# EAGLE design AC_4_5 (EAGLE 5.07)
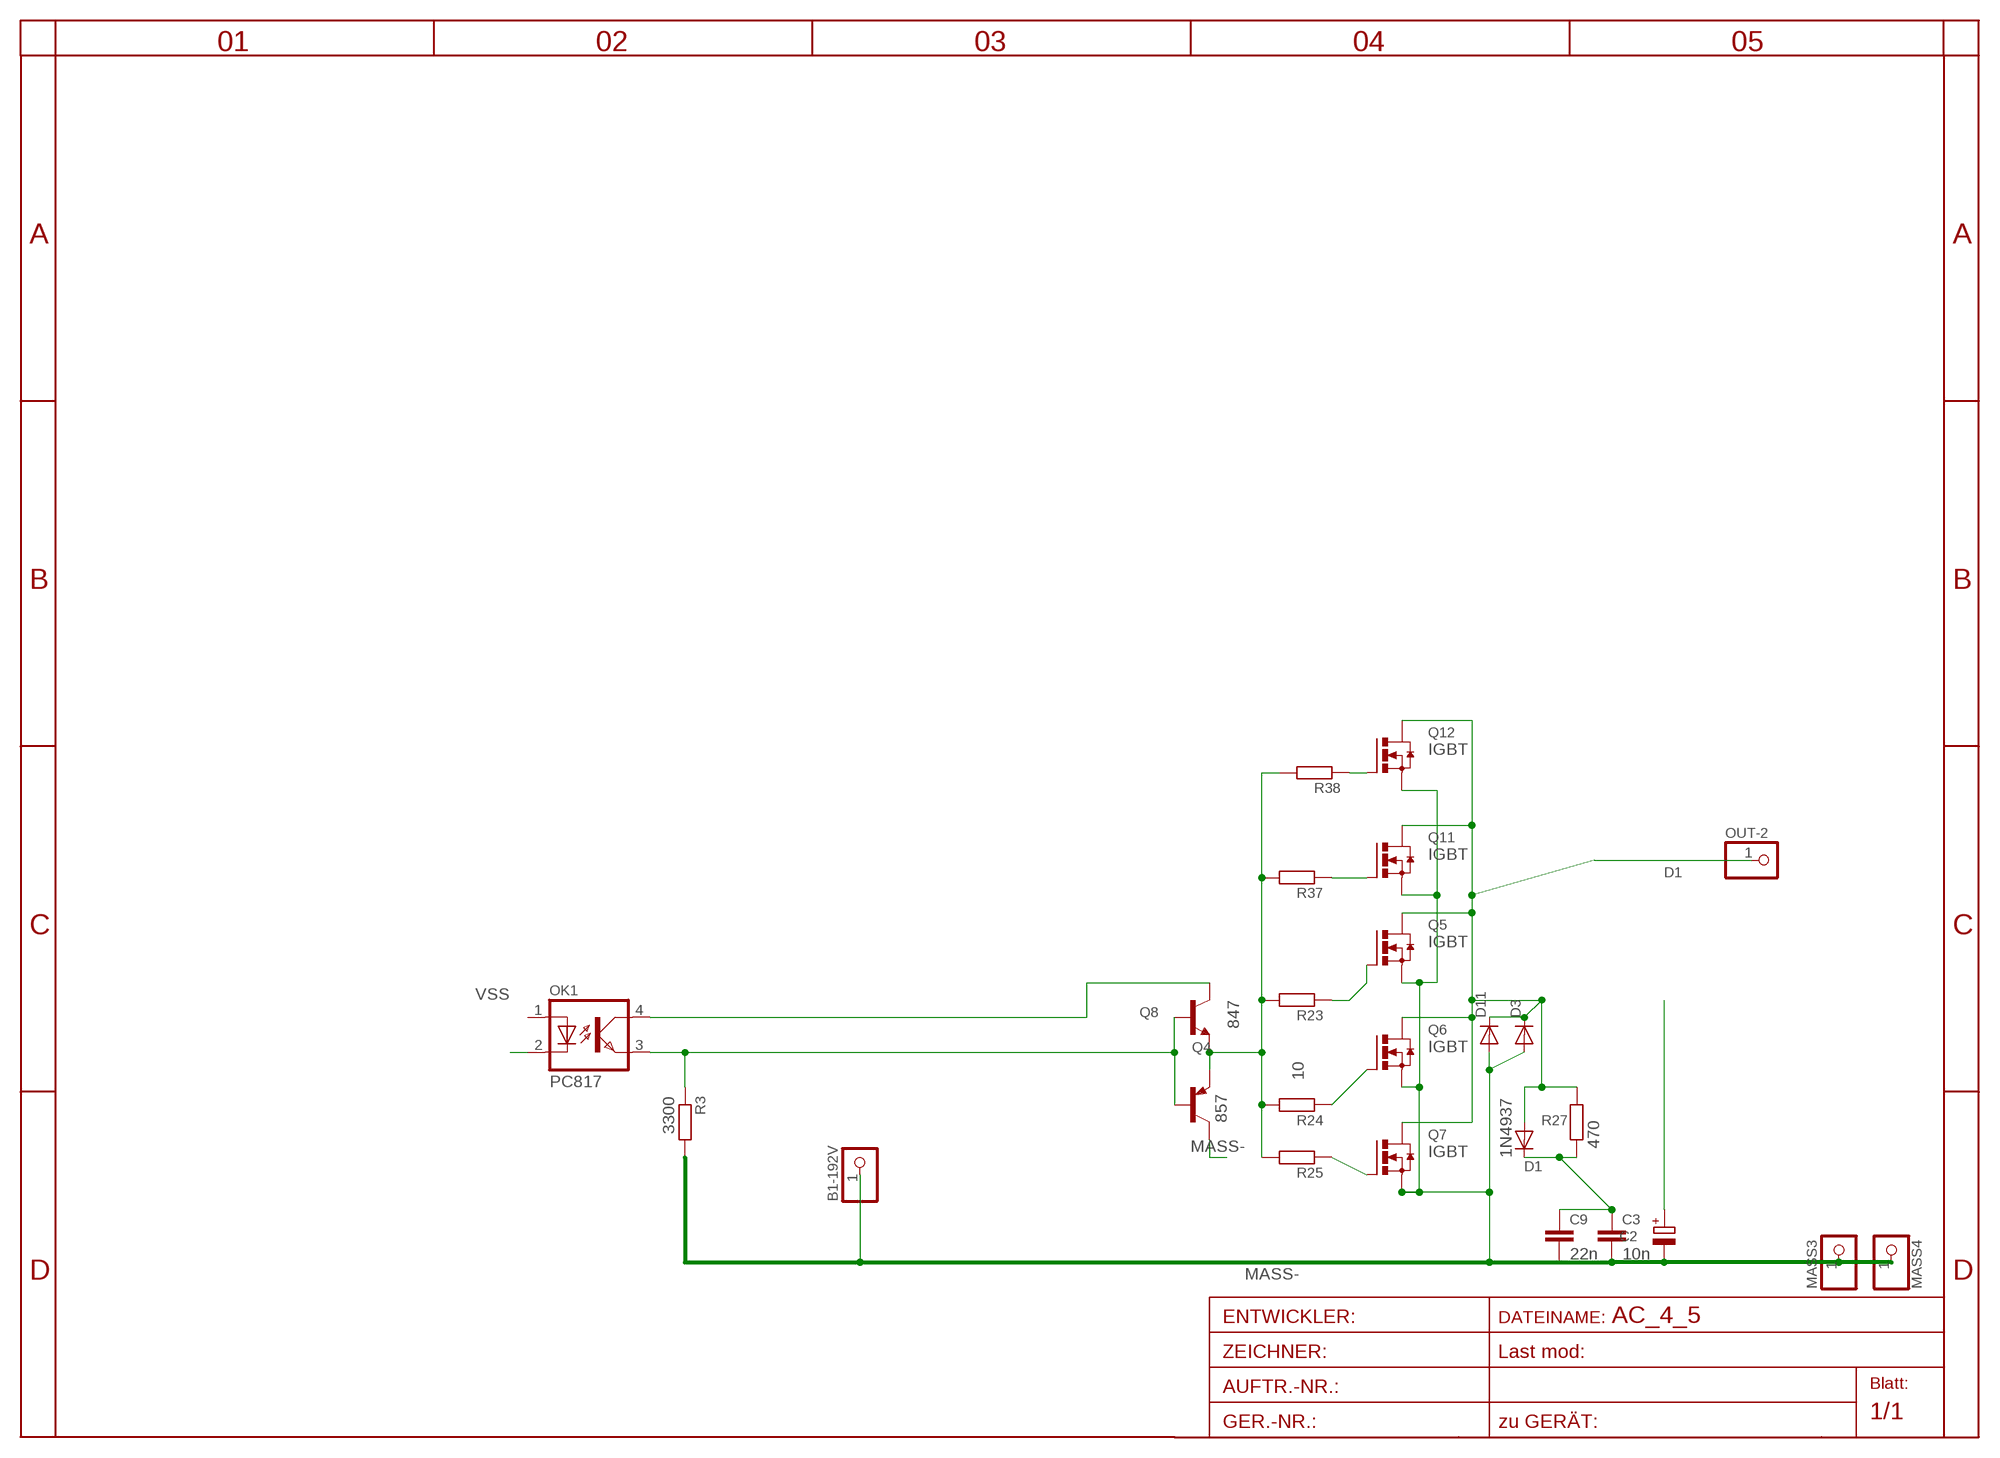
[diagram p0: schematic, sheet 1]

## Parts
B1-192V  PINHD-1X13MM2  [1X3MM2]
C2  CPOL-EUE2.5-5  [E2,5-5]
C3  10n  C-EU025_050-050X075  [C025_050-050X075]
C9  22n  C-EU102-043X133  [C102-043X133]
D1  1N4937  1N4004DO41-10  [DO41-10]
D3  DIODE-SMC  [SMC]
D11  DIODE-SMC  [SMC]
MASS3  PINHD-1X13MM2  [1X3MM2]
MASS4  PINHD-1X13MM2  [1X3MM2]
OK1  PC817  [DIL04]
OUT-2  PINHD-1X13MM2  [1X3MM2]
Q4  857  BC857ALT1SMD  [SOT23-BEC]
Q5  IGBT  N-HEXFET_DPAK-  [TO252]
Q6  IGBT  N-HEXFET_DPAK-  [TO252]
Q7  IGBT  N-HEXFET_DPAK-  [TO252]
Q8  847  BC846ALT1SMD  [SOT23]
Q11  IGBT  N-HEXFET_DPAK-  [TO252]
Q12  IGBT  N-HEXFET_DPAK-  [TO252]
R3  3300  R-EU_R0805  [R0805]
R23  R-EU_0207/12  [0207/12]
R24  R-EU_0207/12  [0207/12]
R25  10  R-EU_0207/12  [0207/12]
R27  470  R-EU_0207/10  [0207/10]
R37  R-EU_0207/12  [0207/12]
R38  R-EU_0207/12  [0207/12]

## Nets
D1: D1.A D3.C D11.C OUT-2.1 Q5.3(D) Q6.3(D) Q7.3(D) Q11.3(D) Q12.3(D) R27.2
EGATE: Q4.E Q8.2(E) R23.2 R24.2 R25.2 R37.2 R38.2
MASS-: B1-192V.1 C2.- C3.3 C9.2 D3.A D11.A MASS3.1 MASS4.1 Q4.C Q5.2(S) Q6.2(S) Q7.2(S) Q11.2(S) Q12.2(S) R3.2
N$2: C3.1 C9.1 D1.C R27.1
N$25: Q12.1(G) R38.1
N$26: Q6.1(G) R24.1
N$27: Q5.1(G) R23.1
N$46: Q11.1(G) R37.1
N$47: Q7.1(G) R25.1
PP1: OK1.3(EMIT) Q4.B Q8.1(B) R3.1
V_OK: C2.+ OK1.4(COL) Q8.3(C)
VSS: OK1.2(C)
Unconnected: OK1.1(A)

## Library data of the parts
B1-192V MASS3 MASS4 OUT-2 = pinhead:PINHD-1X1: PIN HEADER
C2 = rcl-2:CPOL-EU: POLARIZED CAPACITOR, European symbol
C3 C9 = rcl-2:C-EU: CAPACITOR, European symbol
D1 = diode:1N4004: DIODE
D3 D11 = diode:DIODE-: DIODE
OK1 = optocoupler:PC817: SHARP OPTO COUPLER
Q4 = transistor-pnp:BC857*: PNP Transistror
Q5-Q7 Q11 Q12 = transistor-power:N-HEXFET_?-*: HEXFET® Power MOSFET
Q8 = transistor-npn:BC846*: NPN Transistor
R3 R23-R25 R27 R37 R38 = rcl-2:R-EU_: RESISTOR, European symbol

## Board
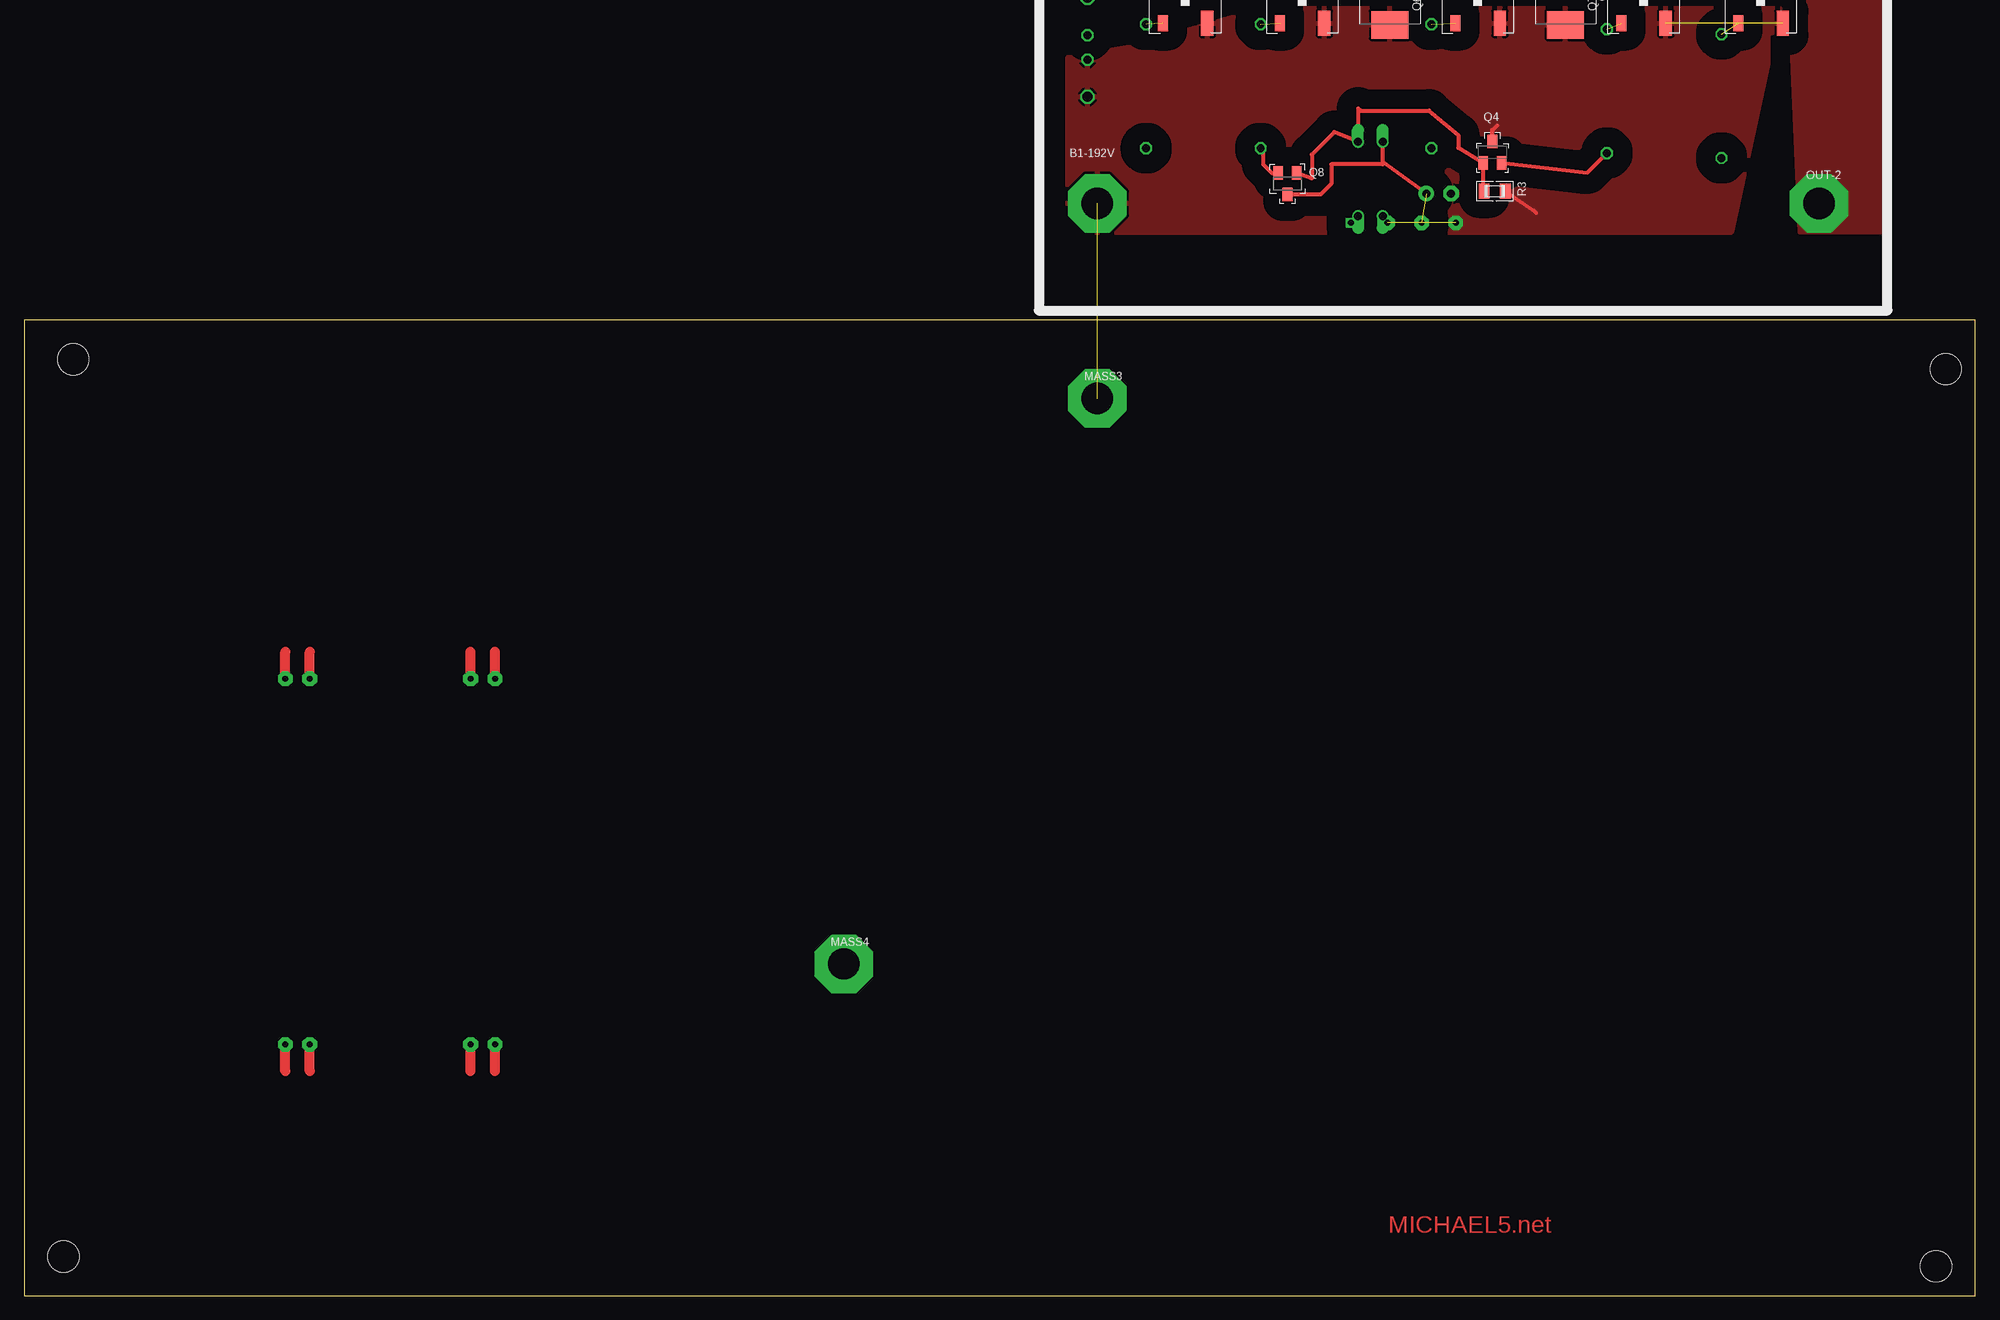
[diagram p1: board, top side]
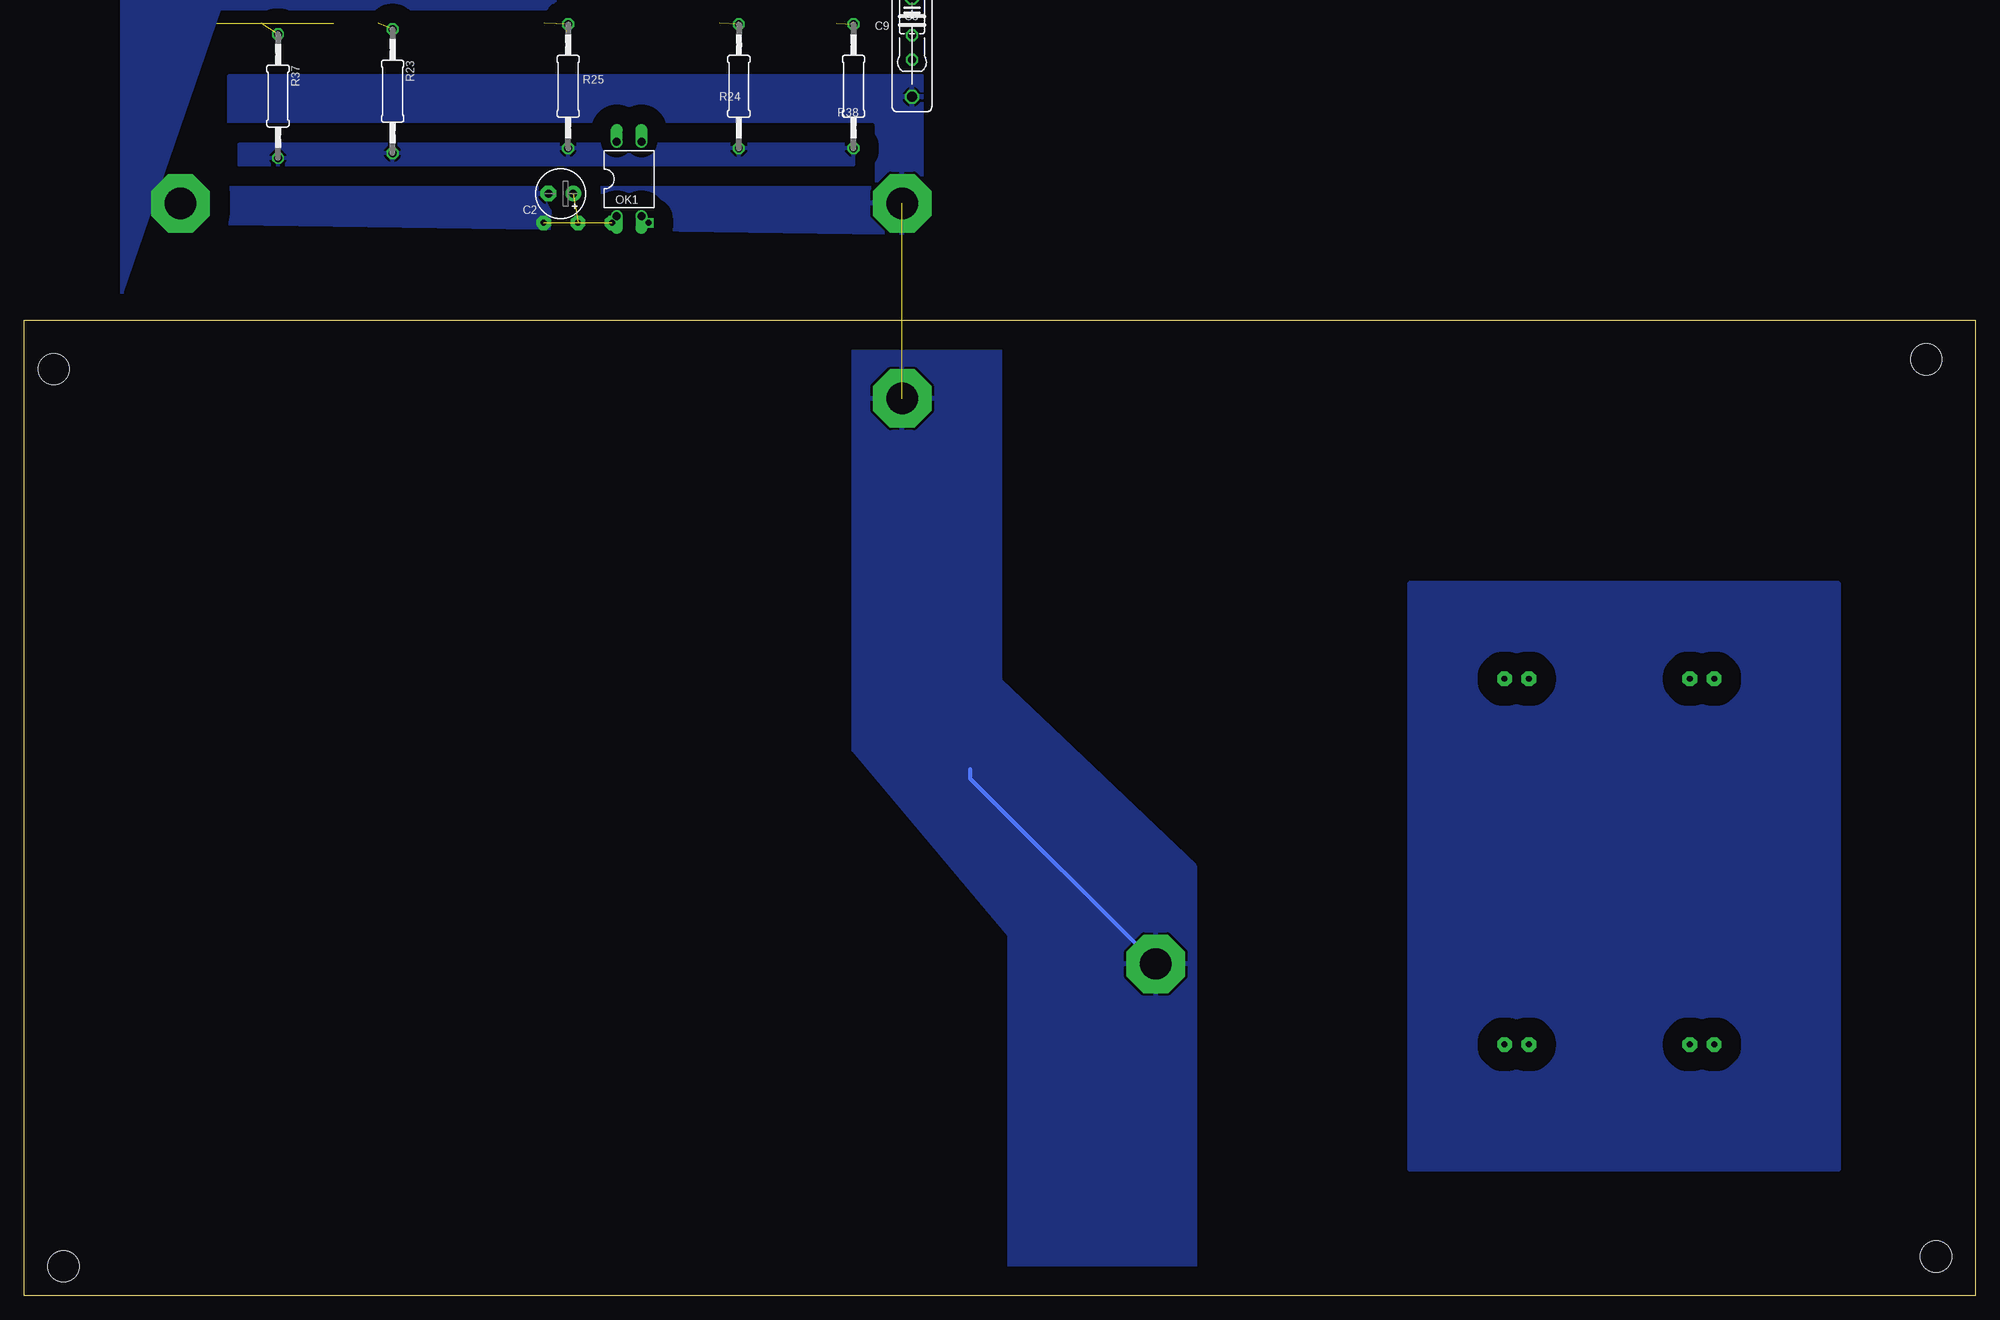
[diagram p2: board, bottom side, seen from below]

Size 200 x 100 mm. Coordinates in mm from the lower left corner, seen from the top.
Outline: 0,0 200,0 200,100 0,100 0,0
Copper layers (1*16): Top 0.035mm / dielectric 1.5mm / Bottom 0.035mm
Design rules "default *": minimum track width 12mil, minimum drill 24mil, track to track 8mil, track to pad 8mil, pad to pad 8mil, via to via 8mil, smd to smd 8mil, copper to edge 40mil, drill to drill 8mil, minimum pad ring 8mil, minimum via ring 8mil, stop-mask expansion 4mil, vias tented up to drill 0mil, thermal gap 10mil
Holes 3.2 mm at 5,96 4,4 197,95 196,3

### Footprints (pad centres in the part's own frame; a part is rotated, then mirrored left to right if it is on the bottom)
1X3MM2 = drill 3.2 pad 6 octagon: 1 0,0
E2,5-5 = drill 0.813 pad 1.6 round: + -1.27,0 | drill 0.813 pad 1.6 octagon: - 1.27,0
C025_050-050X075 = drill 0.813 octagon: 1 -3.81,0; 2 0,0; 3 2.54,0
C102-043X133 = drill 1.016 octagon: 1 -5.08,0; 2 5.08,0
DO41-10 = drill 0.8 octagon: A 5.08,0 | drill 0.8 round: C -5.08,0
SMC = smd 2.8 x 3.8: A 3.7,0; C -3.7,0
DIL04 = drill 0.813 offset: 1 -1.27,-3.81; 2 1.27,-3.81; 3 1.27,3.81; 4 -1.27,3.81
SOT23-BEC = smd 1 x 1.4: B -0.95,-1.1; C 0,1.1; E 0.95,-1.1
TO252 = smd 1 x 1.6: 1 -2.28,-3.53 | smd 1.27 x 2.54: 2 2.28,-3.53 | smd 5.4 x 6.2: 3 0,3.77
SOT23 = smd 1 x 1.4: 1 -0.95,-1.1; 2 0.95,-1.1; 3 0,1.1
R0805 = smd 1.1 x 1.5: 1 -1.1,0; 2 1.1,0
0207/12 = drill 0.813 octagon: 1 -6.35,0; 2 6.35,0
0207/10 = drill 0.813 octagon: 1 -5.08,0; 2 5.08,0

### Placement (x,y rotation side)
B1-192V  not placed on the board
C2  145,113 180 bottom  (outside the outline)
C3  not placed on the board
C9  not placed on the board
D1  not placed on the board
D3  not placed on the board
D11  not placed on the board
MASS3  110,92 0 top
MASS4  84,34 0 top
OK1  138,114.5 0 bottom  (outside the outline)
OUT-2  not placed on the board
Q4  150.5,117.25 0 top  (outside the outline)
Q5  not placed on the board
Q6  not placed on the board
Q7  not placed on the board
Q8  129.5,114 180 top  (outside the outline)
Q11  not placed on the board
Q12  not placed on the board
R3  150.75,113.25 0 top  (outside the outline)
R23  162.25,123.5 270 bottom  (outside the outline)
R24  126.75,124 270 bottom  (outside the outline)
R25  not placed on the board
R27  not placed on the board
R37  not placed on the board
R38  not placed on the board

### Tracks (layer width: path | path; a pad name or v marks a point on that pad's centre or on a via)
D1
  pour Top (isolate 2, rank 2, no thermals): 107,150 190,150 191,109 182,109 181,133 178,134 107,134
  pour Bottom (isolate 2, rank 2, no thermals): 109,148 190,148 190,102.82 180,132 109,132
EGATE
  Top 0.406: Q8.2 127.9,115.1 127,116 127,117.4 R24.2 | Q4.E 160.25,115.15 R23.2
  pour Bottom (isolate 1): 115,118 178,118 178,116 115,116
MASS-  (via drill 0.6 pad 1.5)  (3 unrouted)
  Top 0.406: R3.2 154.75,111.25 155,111 | Q4.C 150.5,119.5 151,120
  Bottom 0.406: 103,54 103,53 MASS4.1
  other vias: 139.75,110 146.75,110
  pour Top (isolate 2, rank 3): 107,127 113,128 127,132 180,132 175,109 107,109
  pour Bottom (isolate 2, rank 3): 108,125 179,125 179,110 108,109
  pour Bottom (isolate 3, rank 4): 100,98 115,98 115,56 99,37 99,3 80,3 80,44 100,63
N$1  (via drill 0.6)
  other vias: 136,110
N$2  (3 unrouted)
N$5  (via drill 0.6 pad 1.5)
  Top 1: 48.25,23 v48.25,25.75
N$8  (via drill 0.6 pad 1.5)
  other vias: 45.75,25.75
N$10  (via drill 0.6 pad 1.5)
  other vias: 26.75,25.75
N$18  (via drill 0.6 pad 1.5)
  Top 1: 29.25,23 v29.25,25.75
N$19  (via drill 0.6 pad 1.5)
  Top 1: v48.25,63.25 48.25,66
N$25  (1 unrouted)
N$26  (1 unrouted)
N$27  (1 unrouted)
N$28  (via drill 0.6 pad 1.5)
  Top 1: v45.75,63.25 45.75,66
N$29  (via drill 0.6 pad 1.5)
  Top 1: v29.25,63.25 29.25,66
N$30  (via drill 0.6 pad 1.5)
  Top 1: v26.75,63.25 26.75,66
N$31
  Top 1: 45.75,23 45.75,25.5
N$32
  Top 1: 26.75,23 26.75,25.5
N$46  (1 unrouted)
N$47  (1 unrouted)
PP1
  Top 0.406: Q8.1 132,114.55 132,117 134.31,119.31 OK1.3 136.73,121.73 137,121.5 144,121.5 147,119 147,117.7 Q4.B 149.55,113.35 R3.1
V_OK  (via drill 0.6 pad 1.5)  (1 unrouted)
  Top 0.406: 139.27,116.21 OK1.4 | 139.27,116.21 139.27,116 134,116 134,114 132.9,112.9 Q8.3 | C2.+ 139.27,116.21
  other vias: 143.25,110
VSS
  pour Bottom (isolate 2): 14,73 58,73 58,13 14,13

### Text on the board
Top: MICHAEL5.net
